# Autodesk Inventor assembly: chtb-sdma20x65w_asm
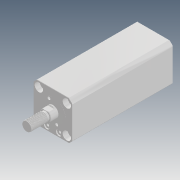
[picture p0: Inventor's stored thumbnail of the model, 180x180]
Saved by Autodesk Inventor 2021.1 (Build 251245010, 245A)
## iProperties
Company: Microsoft
Created: 2018-05
Part Number: chtb-sdma20x65w_asm
Description: STEP AP214
Document SubType Name: Assembly
Designer: user
Title: chtb-sdma20x65w_asm.STEP
Author: Windows
Revision Number: ÈÎºÎ
Sending System: SolidWorks 2015
Preprocessor: SwSTEP 2.0
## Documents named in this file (4)
- D:\Vault_2016\Projekty\Clamptek\Hydraulic\CHTB\CHTB-20\Inventor\CHTB-SDMA20x65W\chtb-sdma20x65w_asm.iam
- D:\Vault_2016\Projekty\Clamptek\Hydraulic\CHTB\CHTB-20\Inventor\CHTB-SDMA20x65W\CHTB-SDMA20X65NBT.ipt
- D:\Vault_2016\Projekty\Clamptek\Hydraulic\CHTB\CHTB-20\Inventor\CHTB-SDMA20x65W\QG_3.ipt
- D:\Vault_2016\Projekty\Clamptek\Hydraulic\CHTB\CHTB-20\Inventor\CHTB-SDMA20x65W\CHTB-SDMA20X65WHSG.ipt
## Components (3 placed, 3 different names)
1. CHTB-SDMA20X65NBT_1
2. QG_3_2
3. CHTB-SDMA20X65WHSG_3
